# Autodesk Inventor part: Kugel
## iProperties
Created: 2007-01
Part Number: Kugel
Cost Center: 0,03 kg
Material: S235JRG2 (1.0038)
Document SubType Name: Modeling
Designer: M. Fiedler
Manufacturer: Standard
Standards Organization: Custom
Einheit: Stück
Ersatzteil: ET AB VT
Grundoberfläche: Rz6.3
WSK a+: 0
WSK a-: -0.1
WSK i+: +0.1
WSK i-: 0
SaveDate: 2007-01-25
SaveTime: 21:26
FileName: Kugel
Masse: 0,03 kg
Author: M. Fiedler
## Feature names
1. Drehung1 [Revolution]
2. Abgeleiteter Körper1 [Tagging]
